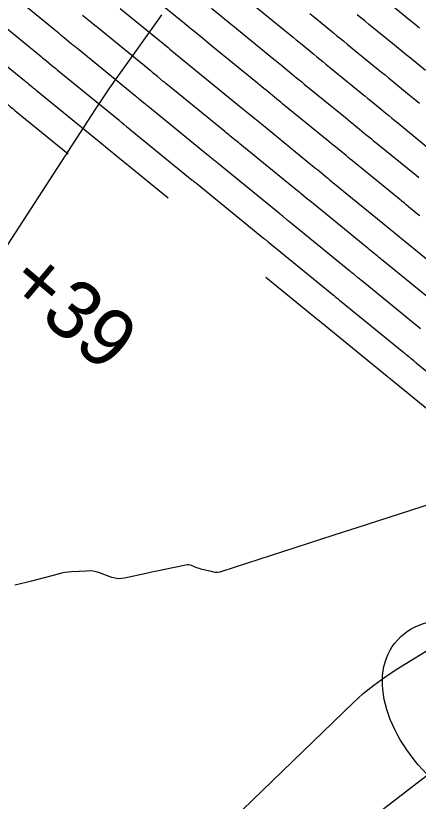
# Model space of a CAD drawing. Extents: x 1005228 to 1008882, y 1883389 to 1885754.
# Drawn here: x 1007830 to 1007871.4, y 1884571 to 1884651.8 of the extents above; entities that cross this region are included whole.
import ezdxf

# ---------------------------------------------------------------- set-up
doc = ezdxf.new("R2010")
doc.units = 0
for name, color, linetype in [('ATDIMS', 7, 'Continuous'), ('C-ANNO-NOTE', 7, 'Continuous'), ('R_Erosion', 7, 'Continuous'), ('S_BASELINE', 7, 'Continuous'), ('TSOBSTACLE', 7, 'Continuous')]:
    doc.layers.add(name, color=color, linetype=linetype)

msp = doc.modelspace()

# ---------------------------------------------------------------- linework, layer by layer
at = {"layer": 'ATDIMS'}
for points in [[(1007850.105, 1884652.601), (1007851.204, 1884651.697), (1007851.479, 1884651.47), (1007851.754, 1884651.245), (1007852.029, 1884651.019), (1007852.305, 1884650.794), (1007856.525, 1884647.349), (1007856.786, 1884647.136), (1007857.046, 1884646.923), (1007857.306, 1884646.709), (1007857.566, 1884646.496), (1007858.605, 1884645.64), (1007858.865, 1884645.426), (1007859.125, 1884645.212), (1007859.386, 1884644.999), (1007859.647, 1884644.786), (1007863.874, 1884641.338), (1007864.138, 1884641.123), (1007864.402, 1884640.907), (1007864.666, 1884640.69), (1007864.929, 1884640.474), (1007865.982, 1884639.607), (1007866.245, 1884639.39), (1007866.509, 1884639.174), (1007866.773, 1884638.958), (1007867.037, 1884638.742), (1007871.137, 1884635.396), (1007871.415, 1884635.17)], [(1007828.231, 1884651.165), (1007832.598, 1884647.604), (1007832.735, 1884647.492), (1007832.871, 1884647.38), (1007833.008, 1884647.268), (1007833.144, 1884647.156), (1007833.69, 1884646.707), (1007833.827, 1884646.595), (1007833.963, 1884646.483), (1007834.1, 1884646.371), (1007834.237, 1884646.259), (1007840.607, 1884641.062), (1007840.671, 1884641.009), (1007840.736, 1884640.956), (1007840.8, 1884640.903), (1007840.865, 1884640.85), (1007841.123, 1884640.638), (1007841.187, 1884640.585), (1007841.252, 1884640.532), (1007841.317, 1884640.479), (1007841.381, 1884640.426), (1007848.139, 1884634.91), (1007848.18, 1884634.876), (1007848.221, 1884634.843), (1007848.262, 1884634.809), (1007848.303, 1884634.775), (1007848.467, 1884634.64), (1007848.508, 1884634.607), (1007848.549, 1884634.573), (1007848.59, 1884634.539), (1007848.631, 1884634.506), (1007855.447, 1884628.947), (1007855.488, 1884628.913), (1007855.529, 1884628.879), (1007855.57, 1884628.846), (1007855.612, 1884628.812), (1007855.776, 1884628.676), (1007855.817, 1884628.642), (1007855.858, 1884628.609), (1007855.9, 1884628.575), (1007855.941, 1884628.541), (1007862.642, 1884623.073), (1007862.696, 1884623.03), (1007862.749, 1884622.986), (1007862.803, 1884622.942), (1007862.856, 1884622.898), (1007863.07, 1884622.722), (1007863.123, 1884622.678), (1007863.177, 1884622.634), (1007863.23, 1884622.59), (1007863.284, 1884622.546), (1007869.888, 1884617.163), (1007869.951, 1884617.112), (1007870.013, 1884617.061), (1007870.075, 1884617.01), (1007870.137, 1884616.959), (1007870.385, 1884616.755), (1007870.447, 1884616.704), (1007870.509, 1884616.653), (1007870.571, 1884616.602), (1007870.633, 1884616.55), (1007870.895, 1884616.335), (1007870.959, 1884616.282), (1007871.023, 1884616.229), (1007871.088, 1884616.176), (1007871.152, 1884616.123), (1007877.685, 1884610.793)]]:
    msp.add_lwpolyline(points, dxfattribs=at)
at = {"layer": 'C-ANNO-NOTE'}
for points in [[(1007828.395, 1884627.053), (1007838.236, 1884642.24), (1007838.914, 1884643.273), (1007839.603, 1884644.297), (1007840.304, 1884645.313), (1007841.016, 1884646.321), (1007844.684, 1884651.449), (1007844.998, 1884651.903)], [(1007873.87, 1884601.972), (1007867.285, 1884599.863), (1007866.109, 1884599.486), (1007864.935, 1884599.108), (1007863.76, 1884598.728), (1007862.587, 1884598.347), (1007851.183, 1884594.637), (1007850.954, 1884594.579), (1007850.724, 1884594.553), (1007850.492, 1884594.56), (1007850.259, 1884594.599), (1007849.143, 1884594.863), (1007849.002, 1884594.899), (1007848.862, 1884594.941), (1007848.724, 1884594.988), (1007848.588, 1884595.041), (1007848.046, 1884595.262), (1007847.909, 1884595.307), (1007847.771, 1884595.33), (1007847.631, 1884595.332), (1007847.488, 1884595.313), (1007845.151, 1884594.825), (1007844.714, 1884594.733), (1007844.277, 1884594.64), (1007843.841, 1884594.546), (1007843.404, 1884594.451), (1007841.181, 1884593.962), (1007840.849, 1884593.912), (1007840.52, 1884593.909), (1007840.195, 1884593.954), (1007839.872, 1884594.046), (1007838.587, 1884594.509), (1007838.264, 1884594.607), (1007837.935, 1884594.672), (1007837.602, 1884594.703), (1007837.264, 1884594.699), (1007835.767, 1884594.61), (1007835.405, 1884594.579), (1007835.046, 1884594.531), (1007834.691, 1884594.464), (1007834.337, 1884594.38), (1007831.624, 1884593.662), (1007831.054, 1884593.514), (1007830.483, 1884593.369), (1007829.911, 1884593.228)], [(1007851.193, 1884568.098), (1007864.675, 1884581.137), (1007865.709, 1884582.084), (1007866.79, 1884582.971), (1007867.919, 1884583.797), (1007869.094, 1884584.562), (1007875.398, 1884588.427)], [(1007865.877, 1884568.776), (1007878.42, 1884578.419), (1007878.633, 1884578.561), (1007878.859, 1884578.67), (1007879.098, 1884578.746), (1007879.35, 1884578.789), (1007880.9, 1884578.948), (1007880.904, 1884578.948), (1007880.909, 1884578.945), (1007880.91, 1884578.944), (1007880.91, 1884578.942), (1007874.036, 1884567.776)]]:
    msp.add_lwpolyline(points, dxfattribs=at)
at = {"layer": 'R_Erosion'}
msp.add_ellipse((1007879.729, 1884578.828), major_axis=(10.768, -8.465), ratio=0.638788, dxfattribs=at)
at = {"layer": 'TSOBSTACLE'}
for points in [[(1007818.074, 1884655.591), (1007822.994, 1884651.576), (1007823.804, 1884650.915), (1007824.613, 1884650.255), (1007825.423, 1884649.594), (1007826.233, 1884648.934), (1007830.894, 1884645.133), (1007830.993, 1884645.052), (1007831.091, 1884644.972), (1007831.19, 1884644.891), (1007831.288, 1884644.81), (1007831.681, 1884644.487), (1007831.779, 1884644.406), (1007831.878, 1884644.326), (1007831.976, 1884644.245), (1007832.075, 1884644.165), (1007838.927, 1884638.573), (1007838.972, 1884638.537), (1007839.017, 1884638.5), (1007839.107, 1884638.426), (1007839.152, 1884638.389), (1007839.196, 1884638.352), (1007845.665, 1884633.072)], [(1007871.524, 1884631.217), (1007871.292, 1884631.407), (1007870.366, 1884632.171), (1007870.135, 1884632.361), (1007869.903, 1884632.552), (1007869.671, 1884632.742), (1007869.438, 1884632.932), (1007864.818, 1884636.702), (1007864.598, 1884636.881), (1007864.379, 1884637.061), (1007864.16, 1884637.241), (1007863.941, 1884637.421), (1007863.066, 1884638.141), (1007862.847, 1884638.321), (1007862.627, 1884638.501), (1007862.408, 1884638.681), (1007862.189, 1884638.86), (1007857.443, 1884642.73), (1007857.227, 1884642.907), (1007857.01, 1884643.084), (1007856.794, 1884643.262), (1007856.578, 1884643.44), (1007855.714, 1884644.152), (1007855.497, 1884644.329), (1007855.281, 1884644.507), (1007855.065, 1884644.684), (1007854.848, 1884644.861), (1007850.12, 1884648.72), (1007849.887, 1884648.911), (1007849.654, 1884649.102), (1007849.421, 1884649.293), (1007849.188, 1884649.485), (1007848.257, 1884650.251), (1007848.024, 1884650.442), (1007847.791, 1884650.634), (1007847.558, 1884650.825), (1007847.324, 1884651.015), (1007842.885, 1884654.638)], [(1007815.625, 1884653.728), (1007820.851, 1884649.463), (1007821.697, 1884648.773), (1007822.543, 1884648.083), (1007823.389, 1884647.393), (1007824.235, 1884646.703), (1007829.191, 1884642.662), (1007829.251, 1884642.613), (1007829.312, 1884642.564), (1007829.372, 1884642.514), (1007829.432, 1884642.465), (1007829.672, 1884642.267), (1007829.732, 1884642.218), (1007829.792, 1884642.168), (1007829.853, 1884642.119), (1007829.913, 1884642.07), (1007835.396, 1884637.596)], [(1007871.598, 1884619.615), (1007865.518, 1884624.571), (1007865.42, 1884624.651), (1007865.322, 1884624.732), (1007865.223, 1884624.812), (1007865.125, 1884624.893), (1007864.734, 1884625.216), (1007864.636, 1884625.297), (1007864.538, 1884625.377), (1007864.439, 1884625.458), (1007864.341, 1884625.538), (1007858.16, 1884630.581), (1007858.074, 1884630.652), (1007857.989, 1884630.722), (1007857.903, 1884630.792), (1007857.817, 1884630.862), (1007857.475, 1884631.144), (1007857.389, 1884631.215), (1007857.304, 1884631.285), (1007857.218, 1884631.355), (1007857.132, 1884631.425), (1007850.834, 1884636.562), (1007850.749, 1884636.631), (1007850.664, 1884636.701), (1007850.579, 1884636.77), (1007850.495, 1884636.84), (1007850.156, 1884637.119), (1007850.071, 1884637.189), (1007849.986, 1884637.259), (1007849.901, 1884637.328), (1007849.816, 1884637.398), (1007843.566, 1884642.5), (1007843.459, 1884642.587), (1007843.352, 1884642.674), (1007843.246, 1884642.762), (1007843.139, 1884642.849), (1007842.713, 1884643.2), (1007842.606, 1884643.288), (1007842.5, 1884643.375), (1007842.393, 1884643.463), (1007842.286, 1884643.55), (1007836.399, 1884648.354), (1007836.224, 1884648.497), (1007836.049, 1884648.64), (1007835.874, 1884648.784), (1007835.699, 1884648.927), (1007835.001, 1884649.502), (1007834.826, 1884649.645), (1007834.651, 1884649.788), (1007834.476, 1884649.932), (1007834.301, 1884650.075), (1007830.228, 1884653.396)], [(1007854.49, 1884652.868), (1007858.203, 1884649.837), (1007858.507, 1884649.588), (1007858.811, 1884649.339), (1007859.115, 1884649.089), (1007859.419, 1884648.84), (1007860.633, 1884647.84), (1007860.937, 1884647.59), (1007861.241, 1884647.34), (1007861.545, 1884647.091), (1007861.85, 1884646.842), (1007865.559, 1884643.817), (1007865.868, 1884643.565), (1007866.177, 1884643.312), (1007866.485, 1884643.059), (1007866.792, 1884642.806), (1007868.023, 1884641.793), (1007868.331, 1884641.54), (1007868.639, 1884641.287), (1007868.947, 1884641.035), (1007869.256, 1884640.782), (1007872.837, 1884637.861)], [(1007871.5, 1884650.528), (1007871.058, 1884650.89), (1007870.616, 1884651.251), (1007868.459, 1884653.011)], [(1007873.308, 1884622.068), (1007867.752, 1884626.596), (1007867.609, 1884626.713), (1007867.466, 1884626.83), (1007867.324, 1884626.947), (1007867.181, 1884627.065), (1007866.611, 1884627.534), (1007866.469, 1884627.652), (1007866.326, 1884627.769), (1007866.183, 1884627.886), (1007866.04, 1884628.003), (1007860.379, 1884632.622), (1007860.249, 1884632.728), (1007860.119, 1884632.835), (1007859.989, 1884632.942), (1007859.858, 1884633.049), (1007859.339, 1884633.477), (1007859.209, 1884633.584), (1007859.078, 1884633.69), (1007858.948, 1884633.797), (1007858.818, 1884633.903), (1007853.037, 1884638.618), (1007852.908, 1884638.723), (1007852.78, 1884638.829), (1007852.651, 1884638.934), (1007852.522, 1884639.04), (1007852.008, 1884639.463), (1007851.88, 1884639.569), (1007851.751, 1884639.675), (1007851.622, 1884639.78), (1007851.493, 1884639.886), (1007845.751, 1884644.573), (1007845.602, 1884644.695), (1007845.453, 1884644.817), (1007845.304, 1884644.939), (1007845.155, 1884645.061), (1007844.561, 1884645.55), (1007844.412, 1884645.673), (1007844.263, 1884645.795), (1007844.114, 1884645.917), (1007843.965, 1884646.038), (1007838.561, 1884650.449), (1007838.347, 1884650.623), (1007838.134, 1884650.797), (1007837.921, 1884650.972), (1007837.708, 1884651.147), (1007836.857, 1884651.847)], [(1007840.723, 1884652.543), (1007845.645, 1884648.527), (1007845.836, 1884648.371), (1007846.027, 1884648.214), (1007846.218, 1884648.058), (1007846.409, 1884647.901), (1007847.171, 1884647.273), (1007847.362, 1884647.116), (1007847.553, 1884646.959), (1007847.744, 1884646.803), (1007847.935, 1884646.647), (1007853.171, 1884642.374), (1007853.343, 1884642.232), (1007853.516, 1884642.091), (1007853.689, 1884641.949), (1007853.861, 1884641.807), (1007854.55, 1884641.24), (1007854.722, 1884641.098), (1007854.895, 1884640.957), (1007855.068, 1884640.815), (1007855.24, 1884640.674), (1007860.503, 1884636.382), (1007860.678, 1884636.239), (1007860.853, 1884636.096), (1007861.028, 1884635.952), (1007861.202, 1884635.809), (1007861.9, 1884635.235), (1007862.074, 1884635.091), (1007862.249, 1884634.948), (1007862.424, 1884634.805), (1007862.599, 1884634.662), (1007867.739, 1884630.467), (1007867.927, 1884630.314), (1007868.114, 1884630.16), (1007868.302, 1884630.007), (1007868.489, 1884629.853), (1007869.237, 1884629.236), (1007869.424, 1884629.082), (1007869.611, 1884628.928), (1007869.799, 1884628.775), (1007869.986, 1884628.621), (1007875.018, 1884624.52)], [(1007860.228, 1884652.04), (1007860.576, 1884651.755), (1007860.924, 1884651.47), (1007861.272, 1884651.184), (1007862.661, 1884650.039), (1007863.008, 1884649.754), (1007863.356, 1884649.468), (1007863.704, 1884649.183), (1007864.053, 1884648.899), (1007867.245, 1884646.295), (1007867.598, 1884646.006), (1007867.951, 1884645.718), (1007868.304, 1884645.428), (1007868.656, 1884645.139), (1007870.064, 1884643.979), (1007870.417, 1884643.689), (1007870.769, 1884643.4), (1007871.122, 1884643.111), (1007871.475, 1884642.823)], [(1007872.106, 1884646.165), (1007870.519, 1884647.471), (1007870.123, 1884647.797), (1007869.726, 1884648.123), (1007869.328, 1884648.448), (1007868.93, 1884648.773), (1007866.256, 1884650.955), (1007865.863, 1884651.275), (1007865.471, 1884651.596), (1007865.08, 1884651.917)], [(1007875.604, 1884608.649), (1007868.527, 1884614.424), (1007868.492, 1884614.453), (1007868.456, 1884614.482), (1007868.35, 1884614.57), (1007868.247, 1884614.654), (1007868.213, 1884614.682), (1007868.178, 1884614.71), (1007861.05, 1884620.521), (1007861.023, 1884620.543), (1007860.97, 1884620.587), (1007860.943, 1884620.609), (1007855.7, 1884624.887)]]:
    msp.add_lwpolyline(points, dxfattribs=at)

# ---------------------------------------------------------------- texts
at = {"layer": 'S_BASELINE'}
msp.add_text('+39', height=6, rotation=319.99998, dxfattribs=at).set_placement((1007828.756, 1884623.721))

doc.saveas('drawing.dxf')
